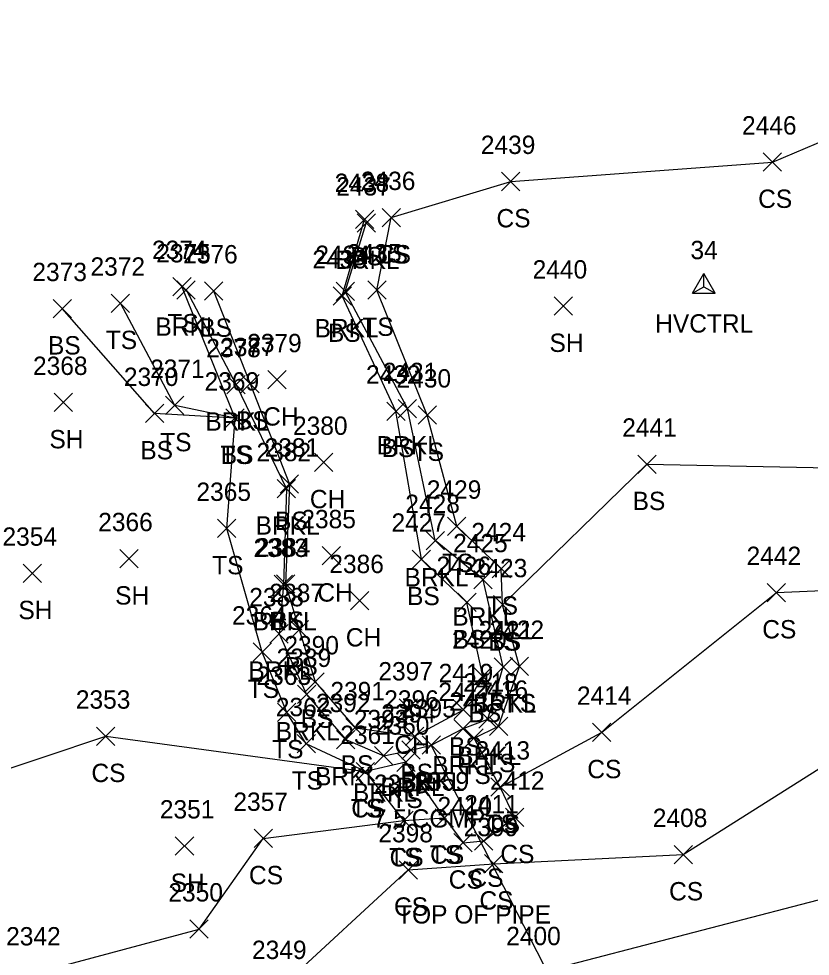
# Model space of a CAD drawing. Extents: x 1502194 to 1507887, y 142265 to 144150.
# Drawn here: x 1506653.1 to 1506739.4, y 143562.8 to 143665 of the extents above; entities that cross this region are included whole.
import ezdxf

# ---------------------------------------------------------------- set-up
doc = ezdxf.new("R2010")
doc.units = 0
for name, color, linetype in [('C_A', 7, 'Continuous'), ('C_I', 7, 'Continuous'), ('CPSM', 7, 'Continuous'), ('D_A', 7, 'Continuous'), ('D_C', 7, 'Continuous'), ('D_I', 7, 'Continuous'), ('D_TIC', 7, 'Continuous'), ('DCP', 7, 'Continuous'), ('L_A', 7, 'Continuous'), ('L_C', 7, 'Continuous'), ('L_I', 7, 'Continuous'), ('L_TIC', 7, 'Continuous'), ('LAWE', 7, 'Continuous'), ('LELB', 7, 'Continuous')]:
    doc.layers.add(name, color=color, linetype=linetype)

msp = doc.modelspace()

# ---------------------------------------------------------------- linework, layer by layer
at = {"layer": 'CPSM'}
for p, q in [((1506726.51, 143635.09), (1506727.76, 143637.26)), ((1506729.01, 143635.09), (1506727.76, 143637.26)), ((1506727.76, 143635.81), (1506727.76, 143637.26)), ((1506726.51, 143635.09), (1506727.76, 143635.81)), ((1506727.76, 143635.81), (1506727.76, 143635.81)), ((1506727.76, 143635.81), (1506729.01, 143635.09)), ((1506726.51, 143635.09), (1506729.01, 143635.09))]:
    msp.add_line(p, q, dxfattribs=at)
at = {"layer": 'D_TIC'}
for points in [[(1506697.03, 143584.85), (1506699.03, 143586.85)], [(1506699.03, 143584.85), (1506697.03, 143586.85)]]:
    msp.add_lwpolyline(points, dxfattribs=at)
at = {"layer": 'DCP'}
msp.add_lwpolyline([(1506777.4, 143431.12), (1506698.03, 143585.85)], dxfattribs=at)
at = {"layer": 'L_TIC'}
for points in [[(1506734.24, 143648.4), (1506736.24, 143650.4)], [(1506736.24, 143648.4), (1506734.24, 143650.4)], [(1506705.7, 143646.28), (1506707.7, 143648.28)], [(1506707.7, 143646.28), (1506705.7, 143648.28)], [(1506689.76, 143642.14), (1506691.76, 143644.14)], [(1506691.76, 143642.14), (1506689.76, 143644.14)], [(1506689.94, 143641.75), (1506691.94, 143643.75)], [(1506691.94, 143641.75), (1506689.94, 143643.75)], [(1506692.67, 143642.35), (1506694.67, 143644.35)], [(1506694.67, 143642.35), (1506692.67, 143644.35)], [(1506692.67, 143642.35), (1506694.67, 143644.35)], [(1506694.67, 143642.35), (1506692.67, 143644.35)], [(1506669.85, 143634.83), (1506671.85, 143636.83)], [(1506671.85, 143634.83), (1506669.85, 143636.83)], [(1506670.31, 143634.46), (1506672.31, 143636.46)], [(1506672.31, 143634.46), (1506670.31, 143636.46)], [(1506673.3, 143634.35), (1506675.3, 143636.35)], [(1506675.3, 143634.35), (1506673.3, 143636.35)], [(1506691.11, 143634.45), (1506693.11, 143636.45)], [(1506693.11, 143634.45), (1506691.11, 143636.45)], [(1506687.33, 143633.8), (1506689.33, 143635.8)], [(1506689.33, 143633.8), (1506687.33, 143635.8)], [(1506687.66, 143634.29), (1506689.66, 143636.29)], [(1506689.66, 143634.29), (1506687.66, 143636.29)], [(1506656.8, 143632.42), (1506658.8, 143634.42)], [(1506658.8, 143632.42), (1506656.8, 143634.42)], [(1506663.14, 143633.01), (1506665.14, 143635.01)], [(1506665.14, 143633.01), (1506663.14, 143635.01)], [(1506711.44, 143632.7), (1506713.44, 143634.7)], [(1506713.44, 143632.7), (1506711.44, 143634.7)], [(1506675.76, 143624.12), (1506677.76, 143626.12)], [(1506677.76, 143624.12), (1506675.76, 143626.12)], [(1506677.28, 143624.24), (1506679.28, 143626.24)], [(1506679.28, 143624.24), (1506677.28, 143626.24)], [(1506680.23, 143624.67), (1506682.23, 143626.67)], [(1506682.23, 143624.67), (1506680.23, 143626.67)], [(1506656.92, 143622.19), (1506658.92, 143624.19)], [(1506658.92, 143622.19), (1506656.92, 143624.19)], [(1506669.07, 143621.87), (1506671.07, 143623.87)], [(1506671.07, 143621.87), (1506669.07, 143623.87)], [(1506693.18, 143621.24), (1506695.18, 143623.24)], [(1506695.18, 143621.24), (1506693.18, 143623.24)], [(1506694.44, 143621.52), (1506696.44, 143623.52)], [(1506696.44, 143621.52), (1506694.44, 143623.52)], [(1506666.87, 143620.99), (1506668.87, 143622.99)], [(1506668.87, 143620.99), (1506666.87, 143622.99)], [(1506675.64, 143620.49), (1506677.64, 143622.49)], [(1506677.64, 143620.49), (1506675.64, 143622.49)], [(1506675.64, 143620.49), (1506677.64, 143622.49)], [(1506677.64, 143620.49), (1506675.64, 143622.49)], [(1506675.64, 143620.49), (1506677.64, 143622.49)], [(1506677.64, 143620.49), (1506675.64, 143622.49)], [(1506696.6, 143620.82), (1506698.6, 143622.82)], [(1506698.6, 143620.82), (1506696.6, 143622.82)], [(1506685.31, 143615.66), (1506687.31, 143617.66)], [(1506687.31, 143615.66), (1506685.31, 143617.66)], [(1506720.55, 143615.46), (1506722.55, 143617.46)], [(1506722.55, 143615.46), (1506720.55, 143617.46)], [(1506681.57, 143613.29), (1506683.57, 143615.29)], [(1506683.57, 143613.29), (1506681.57, 143615.29)], [(1506681.24, 143612.79), (1506683.24, 143614.79)], [(1506683.24, 143612.79), (1506681.24, 143614.79)], [(1506674.74, 143608.46), (1506676.74, 143610.46)], [(1506676.74, 143608.46), (1506674.74, 143610.46)], [(1506699.82, 143608.7), (1506701.82, 143610.7)], [(1506701.82, 143608.7), (1506699.82, 143610.7)], [(1506697.47, 143607.14), (1506699.47, 143609.14)], [(1506699.47, 143607.14), (1506697.47, 143609.14)], [(1506664.09, 143605.16), (1506666.09, 143607.16)], [(1506666.09, 143605.16), (1506664.09, 143607.16)], [(1506686.13, 143605.48), (1506688.13, 143607.48)], [(1506688.13, 143605.48), (1506686.13, 143607.48)], [(1506695.96, 143605.1), (1506697.96, 143607.1)], [(1506697.96, 143605.1), (1506695.96, 143607.1)], [(1506704.67, 143604.06), (1506706.67, 143606.06)], [(1506706.67, 143604.06), (1506704.67, 143606.06)], [(1506653.54, 143603.57), (1506655.54, 143605.57)], [(1506655.54, 143603.57), (1506653.54, 143605.57)], [(1506702.68, 143602.87), (1506704.68, 143604.87)], [(1506704.68, 143602.87), (1506702.68, 143604.87)], [(1506680.91, 143602.35), (1506682.91, 143604.35)], [(1506682.91, 143602.35), (1506680.91, 143604.35)], [(1506681.16, 143602.4), (1506683.16, 143604.4)], [(1506683.16, 143602.4), (1506681.16, 143604.4)], [(1506689.24, 143600.59), (1506691.24, 143602.59)], [(1506691.24, 143600.59), (1506689.24, 143602.59)], [(1506734.68, 143601.47), (1506736.68, 143603.47)], [(1506736.68, 143601.47), (1506734.68, 143603.47)], [(1506700.93, 143600.39), (1506702.93, 143602.39)], [(1506702.93, 143600.39), (1506700.93, 143602.39)], [(1506704.82, 143600.14), (1506706.82, 143602.14)], [(1506706.82, 143600.14), (1506704.82, 143602.14)], [(1506704.82, 143600.14), (1506706.82, 143602.14)], [(1506706.82, 143600.14), (1506704.82, 143602.14)], [(1506680.45, 143596.97), (1506682.45, 143598.97)], [(1506682.45, 143596.97), (1506680.45, 143598.97)], [(1506682.65, 143597.43), (1506684.65, 143599.43)], [(1506684.65, 143597.43), (1506682.65, 143599.43)], [(1506678.61, 143594.98), (1506680.61, 143596.98)], [(1506680.61, 143594.98), (1506678.61, 143596.98)], [(1506704.89, 143593.37), (1506706.89, 143595.37)], [(1506706.89, 143593.37), (1506704.89, 143595.37)], [(1506706.65, 143593.42), (1506708.65, 143595.42)], [(1506708.65, 143593.42), (1506706.65, 143595.42)], [(1506684.37, 143591.73), (1506686.37, 143593.73)], [(1506686.37, 143591.73), (1506684.37, 143593.73)], [(1506702.65, 143592.34), (1506704.65, 143594.34)], [(1506704.65, 143592.34), (1506702.65, 143594.34)], [(1506683.44, 143590.36), (1506685.44, 143592.36)], [(1506685.44, 143590.36), (1506683.44, 143592.36)], [(1506681.28, 143588.4), (1506683.28, 143590.4)], [(1506683.28, 143588.4), (1506681.28, 143590.4)], [(1506694.53, 143588.89), (1506696.53, 143590.89)], [(1506696.53, 143588.89), (1506694.53, 143590.89)], [(1506700.54, 143588.7), (1506702.54, 143590.7)], [(1506702.54, 143588.7), (1506700.54, 143590.7)], [(1506703.21, 143587.67), (1506705.21, 143589.67)], [(1506705.21, 143587.67), (1506703.21, 143589.67)], [(1506688.73, 143586.73), (1506690.73, 143588.73)], [(1506690.73, 143586.73), (1506688.73, 143588.73)], [(1506700.5, 143586.64), (1506702.5, 143588.64)], [(1506702.5, 143586.64), (1506700.5, 143588.64)], [(1506704.38, 143586.89), (1506706.38, 143588.89)], [(1506706.38, 143586.89), (1506704.38, 143588.89)], [(1506661.54, 143585.81), (1506663.54, 143587.81)], [(1506663.54, 143585.81), (1506661.54, 143587.81)], [(1506687.72, 143585.44), (1506689.72, 143587.44)], [(1506689.72, 143585.44), (1506687.72, 143587.44)], [(1506695.22, 143585.81), (1506697.22, 143587.81)], [(1506697.22, 143585.81), (1506695.22, 143587.81)], [(1506701.7, 143585.6), (1506703.7, 143587.6)], [(1506703.7, 143585.6), (1506701.7, 143587.6)], [(1506715.61, 143586.23), (1506717.61, 143588.23)], [(1506717.61, 143586.23), (1506715.61, 143588.23)], [(1506683.4, 143584.99), (1506685.4, 143586.99)], [(1506685.4, 143584.99), (1506683.4, 143586.99)], [(1506694.84, 143584.3), (1506696.84, 143586.3)], [(1506696.84, 143584.3), (1506694.84, 143586.3)], [(1506697.03, 143584.85), (1506699.03, 143586.85)], [(1506699.03, 143584.85), (1506697.03, 143586.85)], [(1506691.85, 143583.68), (1506693.85, 143585.68)], [(1506693.85, 143583.68), (1506691.85, 143585.68)], [(1506694.28, 143582.98), (1506696.28, 143584.98)], [(1506696.28, 143582.98), (1506694.28, 143584.98)], [(1506689.86, 143581.96), (1506691.86, 143583.96)], [(1506691.86, 143581.96), (1506689.86, 143583.96)], [(1506689.86, 143581.96), (1506691.86, 143583.96)], [(1506691.86, 143581.96), (1506689.86, 143583.96)], [(1506689.86, 143581.96), (1506691.86, 143583.96)], [(1506691.86, 143581.96), (1506689.86, 143583.96)], [(1506704.55, 143580.26), (1506706.55, 143582.26)], [(1506706.55, 143580.26), (1506704.55, 143582.26)], [(1506704.55, 143580.26), (1506706.55, 143582.26)], [(1506706.55, 143580.26), (1506704.55, 143582.26)], [(1506694.05, 143576.62), (1506696.05, 143578.62)], [(1506696.05, 143576.62), (1506694.05, 143578.62)], [(1506694.05, 143576.62), (1506696.05, 143578.62)], [(1506696.05, 143576.62), (1506694.05, 143578.62)], [(1506698.47, 143576.91), (1506700.47, 143578.91)], [(1506700.47, 143576.91), (1506698.47, 143578.91)], [(1506698.47, 143576.91), (1506700.47, 143578.91)], [(1506700.47, 143576.91), (1506698.47, 143578.91)], [(1506706.13, 143576.97), (1506708.13, 143578.97)], [(1506708.13, 143576.97), (1506706.13, 143578.97)], [(1506678.72, 143574.67), (1506680.72, 143576.67)], [(1506680.72, 143574.67), (1506678.72, 143576.67)], [(1506700.5, 143574.19), (1506702.5, 143576.19)], [(1506702.5, 143574.19), (1506700.5, 143576.19)], [(1506702.76, 143574.39), (1506704.76, 143576.39)], [(1506704.76, 143574.39), (1506702.76, 143576.39)], [(1506670.13, 143573.84), (1506672.13, 143575.84)], [(1506672.13, 143573.84), (1506670.13, 143575.84)], [(1506724.52, 143572.91), (1506726.52, 143574.91)], [(1506726.52, 143572.91), (1506724.52, 143574.91)], [(1506694.53, 143571.24), (1506696.53, 143573.24)], [(1506696.53, 143571.24), (1506694.53, 143573.24)], [(1506703.85, 143571.91), (1506705.85, 143573.91)], [(1506705.85, 143571.91), (1506703.85, 143573.91)], [(1506671.72, 143564.79), (1506673.72, 143566.79)], [(1506673.72, 143564.79), (1506671.72, 143566.79)]]:
    msp.add_lwpolyline(points, dxfattribs=at)
at = {"layer": 'LAWE'}
msp.add_lwpolyline([(1506671.31, 143635.46), (1506676.76, 143625.12), (1506682.24, 143613.79), (1506681.91, 143603.35), (1506681.45, 143597.97), (1506684.44, 143591.36), (1506688.72, 143586.44), (1506692.85, 143584.68), (1506695.84, 143585.3), (1506698.03, 143585.85), (1506701.5, 143587.64), (1506704.21, 143588.67), (1506705.89, 143594.37), (1506703.68, 143603.87), (1506698.47, 143608.14), (1506695.44, 143622.52), (1506688.66, 143635.29), (1506690.94, 143642.75)], dxfattribs=at)
at = {"layer": 'LELB'}
for points in [[(1506693.67, 143643.35), (1506706.7, 143647.28), (1506735.24, 143649.4), (1506753.22, 143657.03), (1506800.11, 143665.02)], [(1506705.82, 143601.14), (1506721.55, 143616.46), (1506750.56, 143615.89), (1506769.34, 143629.36), (1506821.65, 143640.49), (1506874.45, 143662.34)], [(1506624.13, 143555.62), (1506640.38, 143556.63), (1506654.94, 143561), (1506672.72, 143565.79), (1506679.72, 143575.67), (1506695.05, 143577.62), (1506699.47, 143577.91), (1506701.5, 143575.19), (1506703.76, 143575.39), (1506707.13, 143577.97), (1506705.55, 143581.26), (1506716.61, 143587.23), (1506735.68, 143602.47), (1506756.62, 143603.39), (1506780.29, 143609.03), (1506830.83, 143625.99), (1506880.34, 143648.95)], [(1506674.3, 143635.35), (1506678.28, 143625.24), (1506682.57, 143614.29), (1506682.16, 143603.4), (1506683.65, 143598.43), (1506685.37, 143592.73), (1506689.73, 143587.73), (1506696.22, 143586.81), (1506701.54, 143589.7), (1506703.65, 143593.34), (1506701.93, 143601.39), (1506696.96, 143606.1), (1506694.18, 143622.24), (1506688.33, 143634.8), (1506690.76, 143643.14)], [(1506705.55, 143581.26), (1506702.7, 143586.6), (1506705.38, 143587.89), (1506707.65, 143594.42), (1506705.82, 143601.14), (1506705.67, 143605.06), (1506700.82, 143609.7), (1506697.6, 143621.82), (1506692.11, 143635.45), (1506693.67, 143643.35)], [(1506695.05, 143577.62), (1506690.86, 143582.96), (1506684.4, 143585.99), (1506682.28, 143589.4), (1506679.61, 143595.98), (1506675.74, 143609.46), (1506676.64, 143621.49), (1506670.85, 143635.83)], [(1506676.64, 143621.49), (1506667.87, 143621.99), (1506657.8, 143633.42)], [(1506676.64, 143621.49), (1506670.07, 143622.87), (1506664.14, 143634.01)], [(1506517.85, 143501.34), (1506567.89, 143522.62), (1506612.11, 143536.7), (1506661.61, 143547.98), (1506681.76, 143559.52), (1506695.53, 143572.24), (1506704.85, 143572.91), (1506725.52, 143573.91), (1506746.5, 143587.18), (1506797.75, 143604.14), (1506837.79, 143614.31), (1506888.27, 143631.28)], [(1506520.26, 143493.12), (1506571.84, 143512.42), (1506617.89, 143527.46), (1506663.2, 143542.3), (1506684.6, 143550.02), (1506709.64, 143561.03), (1506743.74, 143569.88), (1506756.3, 143575.97), (1506802.67, 143594.79), (1506845.42, 143601.65), (1506896.99, 143614.38)], [(1506641.69, 143579.85), (1506662.54, 143586.81), (1506690.86, 143582.96)], [(1506699.47, 143577.91), (1506695.28, 143583.98), (1506690.86, 143582.96)]]:
    msp.add_lwpolyline(points, dxfattribs=at)

# ---------------------------------------------------------------- texts
at = {"layer": 'C_A'}
msp.add_text('HVCTRL', height=2, dxfattribs=at).set_placement((1506722.45, 143630.81))
at = {"layer": 'C_I'}
msp.add_text('34', height=2, dxfattribs=at).set_placement((1506726.3, 143638.81))
at = {"layer": 'D_A'}
msp.add_text('P', height=2, dxfattribs=at).set_placement((1506697.4, 143580.85))
at = {"layer": 'D_C'}
msp.add_text("7.5'CGMP", height=2, dxfattribs=at).set_placement((1506691.67, 143576.85))
at = {"layer": 'D_I'}
msp.add_text('2395', height=2, dxfattribs=at).set_placement((1506694.77, 143588.85))
at = {"layer": 'L_A'}
for s, p in [('CS', (1506733.68, 143644.4)), ('CS', (1506705.15, 143642.28)), ('BRKL', (1506687.59, 143637.75)), ('BS', (1506689.2, 143638.14)), ('TS', (1506692.08, 143638.35)), ('CS', (1506692.11, 143638.35)), ('BRKL', (1506667.96, 143630.46)), ('TS', (1506669.26, 143630.83)), ('BS', (1506672.74, 143630.35)), ('BRKL', (1506685.31, 143630.29)), ('TS', (1506690.52, 143630.45)), ('BS', (1506686.77, 143629.8)), ('BS', (1506656.24, 143628.42)), ('TS', (1506662.55, 143629.01)), ('SH', (1506710.93, 143628.7)), ('BRKL', (1506673.41, 143620.12)), ('BS', (1506676.73, 143620.24)), ('CH', (1506679.71, 143620.67)), ('SH', (1506656.4, 143618.19)), ('BS', (1506666.31, 143616.99)), ('TS', (1506668.48, 143617.87)), ('BRKL', (1506692.09, 143617.52)), ('BS', (1506692.62, 143617.24)), ('TS', (1506675.05, 143616.49)), ('TS', (1506675.05, 143616.49)), ('BS', (1506675.08, 143616.49)), ('TS', (1506696.01, 143616.82)), ('CH', (1506684.8, 143611.66)), ('BS', (1506719.99, 143611.46)), ('BRKL', (1506678.88, 143608.79)), ('BS', (1506681.01, 143609.29)), ('TS', (1506699.23, 143604.7)), ('TS', (1506674.15, 143604.46)), ('BRKL', (1506695.12, 143603.14)), ('SH', (1506663.57, 143601.16)), ('CH', (1506685.62, 143601.48)), ('BS', (1506695.4, 143601.1)), ('SH', (1506653.02, 143599.57)), ('TS', (1506704.08, 143600.06)), ('BRKL', (1506700.33, 143598.87)), ('BRKL', (1506678.56, 143598.35)), ('BS', (1506680.6, 143598.4)), ('CH', (1506688.72, 143596.59)), ('CS', (1506734.13, 143597.47)), ('BS', (1506700.37, 143596.39)), ('TS', (1506704.23, 143596.14)), ('BS', (1506704.26, 143596.14)), ('BS', (1506682.09, 143593.43)), ('BRKL', (1506678.1, 143592.97)), ('TS', (1506678.02, 143590.98)), ('BRKL', (1506702.54, 143589.37)), ('TS', (1506706.06, 143589.42)), ('BS', (1506702.09, 143588.34)), ('BS', (1506683.81, 143587.73)), ('BRKL', (1506681.08, 143586.36)), ('TS', (1506680.69, 143584.4)), ('CH', (1506694.02, 143584.89)), ('BS', (1506699.98, 143584.7)), ('BRKL', (1506700.86, 143583.67)), ('BS', (1506688.17, 143582.73)), ('BRKL', (1506698.14, 143582.64)), ('TS', (1506703.79, 143582.89)), ('CS', (1506715.05, 143582.23)), ('CS', (1506660.98, 143581.81)), ('BRKL', (1506685.37, 143581.44)), ('BS', (1506694.66, 143581.81)), ('TS', (1506701.11, 143581.6)), ('TS', (1506682.81, 143580.99)), ('BRKL', (1506692.49, 143580.3)), ('BRKL', (1506694.67, 143580.85)), ('BRKL', (1506689.49, 143579.68)), ('TS', (1506693.69, 143578.98)), ('TS', (1506689.27, 143577.96)), ('TS', (1506689.27, 143577.96)), ('CS', (1506689.31, 143577.96)), ('TS', (1506703.96, 143576.26)), ('CS', (1506704, 143576.26)), ('CS', (1506705.57, 143572.97)), ('TS', (1506693.45, 143572.62)), ('CS', (1506693.49, 143572.62)), ('TS', (1506697.88, 143572.91)), ('CS', (1506697.91, 143572.91)), ('CS', (1506678.16, 143570.67)), ('CS', (1506699.94, 143570.19)), ('CS', (1506702.2, 143570.39)), ('SH', (1506669.62, 143569.84)), ('CS', (1506723.97, 143568.91)), ('CS', (1506703.29, 143567.91)), ('CS', (1506693.97, 143567.24))]:
    msp.add_text(s, height=2, dxfattribs=at).set_placement(p)
at = {"layer": 'L_C'}
msp.add_text('TOP OF PIPE', height=2, dxfattribs=at).set_placement((1506694.31, 143566.39))
at = {"layer": 'L_I'}
for s, p in [('2446', (1506731.92, 143652.4)), ('2439', (1506703.44, 143650.28)), ('2438', (1506687.5, 143646.14)), ('2437', (1506687.68, 143645.75)), ('2436', (1506690.36, 143646.35)), ('2436', (1506690.36, 143646.35)), ('2374', (1506667.59, 143638.83)), ('2375', (1506668.05, 143638.46)), ('2435', (1506688.85, 143638.45)), ('2376', (1506670.98, 143638.35)), ('2433', (1506685.07, 143637.8)), ('2434', (1506685.4, 143638.29)), ('2373', (1506654.54, 143636.42)), ('2372', (1506660.88, 143637.01)), ('2440', (1506709.09, 143636.7)), ('2377', (1506675.02, 143628.24)), ('2379', (1506677.96, 143628.67)), ('2378', (1506673.5, 143628.12)), ('2368', (1506654.61, 143626.19)), ('2371', (1506667.38, 143625.87)), ('2432', (1506690.92, 143625.24)), ('2431', (1506692.75, 143625.52)), ('2370', (1506664.52, 143624.99)), ('2369', (1506673.32, 143624.49)), ('2369', (1506673.32, 143624.49)), ('2369', (1506673.32, 143624.49)), ('2430', (1506694.25, 143624.82)), ('2380', (1506682.96, 143619.66)), ('2441', (1506718.86, 143619.46)), ('2381', (1506679.87, 143617.29)), ('2382', (1506678.98, 143616.79)), ('2365', (1506672.43, 143612.46)), ('2429', (1506697.55, 143612.7)), ('2428', (1506695.21, 143611.14)), ('2366', (1506661.72, 143609.16)), ('2385', (1506683.87, 143609.48)), ('2427', (1506693.7, 143609.1)), ('2424', (1506702.41, 143608.06)), ('2354', (1506651.28, 143607.57)), ('2425', (1506700.42, 143606.87)), ('2383', (1506678.65, 143606.35)), ('2384', (1506678.9, 143606.4)), ('2442', (1506732.42, 143605.47)), ('2386', (1506686.92, 143604.59)), ('2426', (1506698.61, 143604.39)), ('2423', (1506702.56, 143604.14)), ('2423', (1506702.56, 143604.14)), ('2388', (1506678.19, 143600.97)), ('2387', (1506680.39, 143601.43)), ('2364', (1506676.31, 143598.98)), ('2421', (1506703.2, 143597.37)), ('2422', (1506704.39, 143597.42)), ('2390', (1506682.02, 143595.73)), ('2420', (1506700.3, 143596.34)), ('2389', (1506681.17, 143594.36)), ('2363', (1506678.98, 143592.4)), ('2397', (1506692.27, 143592.89)), ('2419', (1506698.84, 143592.7)), ('2418', (1506701.52, 143591.67)), ('2391', (1506687.04, 143590.73)), ('2417', (1506698.81, 143590.64)), ('2416', (1506702.64, 143590.89)), ('2353', (1506659.28, 143589.81)), ('2392', (1506685.46, 143589.44)), ('2396', (1506692.91, 143589.81)), ('2415', (1506700, 143589.6)), ('2414', (1506713.92, 143590.23)), ('2362', (1506681.09, 143588.99)), ('2394', (1506692.58, 143588.3)), ('2395', (1506694.77, 143588.85)), ('2393', (1506689.59, 143587.68)), ('2360', (1506691.89, 143586.98)), ('2361', (1506688.12, 143585.96)), ('2361', (1506688.12, 143585.96)), ('2361', (1506688.12, 143585.96)), ('2413', (1506702.86, 143584.26)), ('2413', (1506702.86, 143584.26)), ('2358', (1506691.79, 143580.62)), ('2358', (1506691.79, 143580.62)), ('2359', (1506696.2, 143580.91)), ('2359', (1506696.2, 143580.91)), ('2412', (1506704.44, 143580.97)), ('2357', (1506676.46, 143578.67)), ('2410', (1506698.72, 143578.19)), ('2411', (1506701.63, 143578.39)), ('2351', (1506668.44, 143577.84)), ('2408', (1506722.19, 143576.91)), ('2398', (1506692.27, 143575.24)), ('2399', (1506701.58, 143575.91)), ('2350', (1506669.37, 143568.79)), ('2342', (1506651.68, 143564)), ('2400', (1506706.21, 143564.03)), ('2349', (1506678.49, 143562.52))]:
    msp.add_text(s, height=2, dxfattribs=at).set_placement(p)

doc.saveas('drawing.dxf')
